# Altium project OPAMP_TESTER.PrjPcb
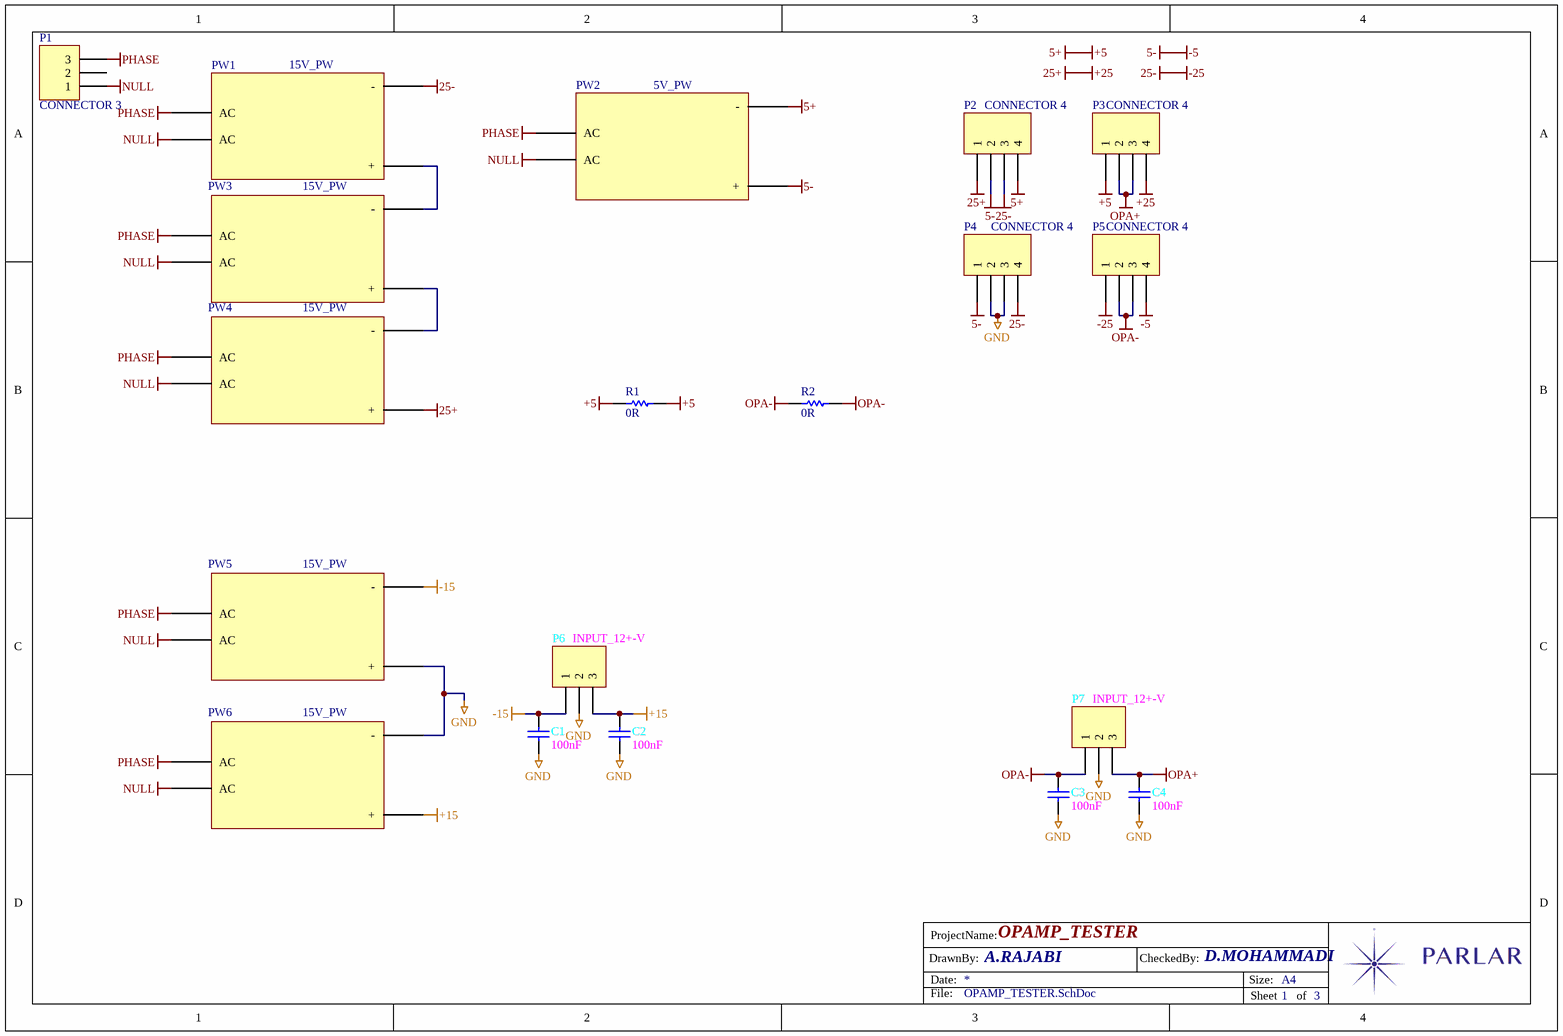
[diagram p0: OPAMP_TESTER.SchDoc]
3 sheets, 148 parts. Net scope: global (net labels, ports and power ports of the same name join across sheets).
Board files: OPAMP_TESTER.PcbDoc, OPAMP_TESTERh.PcbDoc
Sheets:
  OPAMP_TESTER.SchDoc
  OPAMP_TESTER_1.SchDoc
  OPAMP_TESTER_2.SchDoc

## Sheet OPAMP_TESTER.SchDoc: OPAMP_TESTER
size A4; CheckedBy: D.MOHAMMADI; DrawnBy: A.RAJABI; SheetNumber: 1; SheetTotal: 3

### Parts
C1  100nF  [SMD 0805]
C2  100nF  [SMD 0805]
C3  100nF  [SMD 0805]
C4  100nF  [SMD 0805]
P1  CONNECTOR 3  [CON VH 3]
P2  CONNECTOR 4  [CON HDR 2.54M 4]
P3  CONNECTOR 4  [CON HDR 2.54M 4]
P4  CONNECTOR 4  [CON HDR 2.54M 4]
P5  CONNECTOR 4  [CON HDR 2.54M 4]
P6  INPUT_12+-V  [CON XH 3]
P7  INPUT_12+-V  [CON XH 3]
PW1  15V_PW  [POW]
PW2  5V_PW  [POW]
PW3  15V_PW  [POW]
PW4  15V_PW  [POW]
PW5  15V_PW  [POW]
PW6  15V_PW  [POW]
R1  0R  [SMD 1206]
R2  0R  [SMD 1206]

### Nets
+5: P2.4 P3.1 PW2.3(-) R1.1 R1.2  [also labelled 5+]
+15: C2.2 P6.3 PW6.4(+)
+25: P2.1 P3.4 PW4.4(+)  [also labelled 25+]
-5: P2.2 P4.1 P5.4 PW2.4(+)  [also labelled 5-]
-15: C1.2 P6.1 PW5.3(-)
-25: P2.3 P4.4 P5.1 PW1.3(-)  [also labelled 25-]
GND: C1.1 C2.1 C3.1 C4.1 P4.2 P4.3 P6.2 P7.2 PW5.4(+) PW6.3(-)
NULL: P1.1 PW1.2(AC) PW2.2(AC) PW3.2(AC) PW4.2(AC) PW5.2(AC) PW6.2(AC)
OPA+: C4.2 P3.2 P3.3 P7.3
OPA-: C3.2 P5.2 P5.3 P7.1 R2.1 R2.2
PHASE: P1.3 PW1.1(AC) PW2.1(AC) PW3.1(AC) PW4.1(AC) PW5.1(AC) PW6.1(AC)
NetPW1_4: PW1.4(+) PW3.3(-)
NetPW3_4: PW3.4(+) PW4.3(-)

Not connected (* = marked no-connect by the designer): P1 2

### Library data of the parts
C1-C4 = CAP: Capacitor
P1 P6 P7 = CONNECTOR 3: Header, 3-Pin
P2-P5 = CONNECTOR 4: Header, 4-Pin
PW1-PW6 = POWER
R1 R2 = RES: Resistor

## Sheet OPAMP_TESTER_1.SchDoc: OPAMP_TESTER
size A4; CheckedBy: D.MOHAMMADI; DrawnBy: A.RAJABI; SheetNumber: 2; SheetTotal: 3
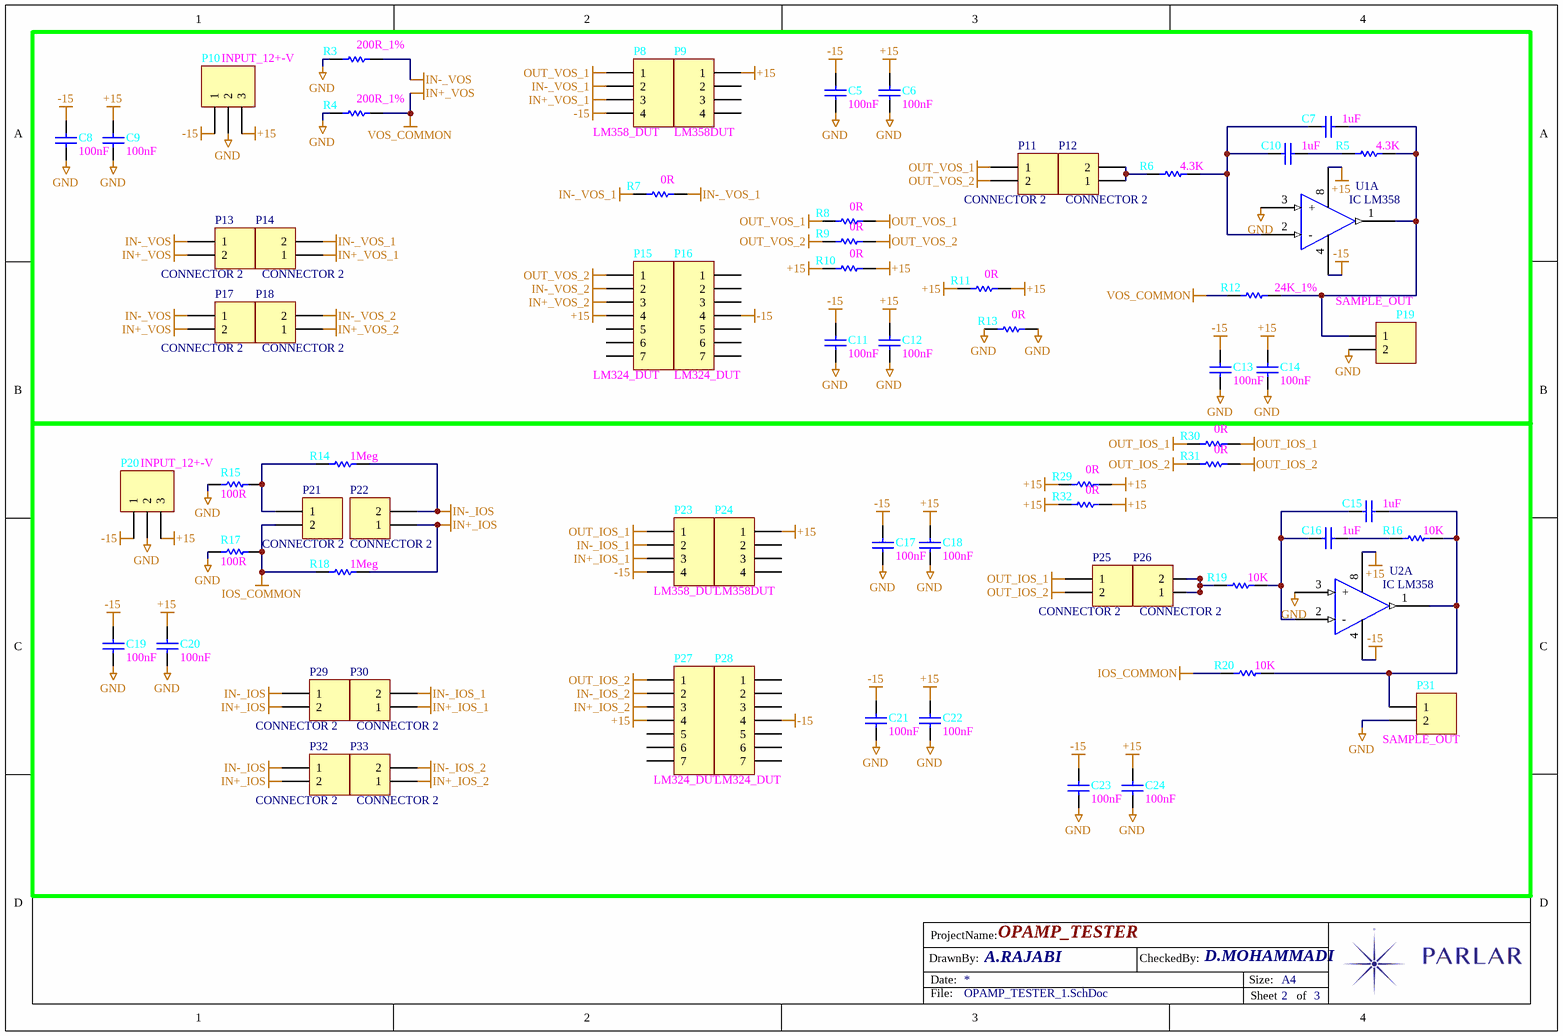
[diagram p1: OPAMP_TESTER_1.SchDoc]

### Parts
C5  100nF  [SMD 0805]
C6  100nF  [SMD 1206]
C7  1uF  [SMD 0805]
C8  100nF  [SMD 0805]
C9  100nF  [SMD 0805]
C10  1uF  [SMD 0805]
C11  100nF  [SMD 0805]
C12  100nF  [SMD 1206]
C13  100nF  [SMD 0805]
C14  100nF  [SMD 0805]
C15  1uF  [SMD 1206]
C16  1uF  [SMD 1206]
C17  100nF  [SMD 0805]
C18  100nF  [SMD 1206]
C19  100nF  [SMD 0805]
C20  100nF  [SMD 0805]
C21  100nF  [SMD 1206]
C22  100nF  [SMD 0805]
C23  100nF  [SMD 0805]
C24  100nF  [SMD 0805]
P8  LM358_DUT  [CON HDR 2.54FM 4]
P9  LM358DUT  [CON HDR 2.54FM 4]
P10  INPUT_12+-V  [CON XH 3]
P11  CONNECTOR 2  [CON HDR 2.54M 2]
P12  CONNECTOR 2  [CON HDR 2.54M 2]
P13  CONNECTOR 2  [CON HDR 2.54M 2]
P14  CONNECTOR 2  [CON HDR 2.54M 2]
P15  LM324_DUT  [CON HDR 2.54FM 7]
P16  LM324_DUT  [CON HDR 2.54FM 7]
P17  CONNECTOR 2  [CON HDR 2.54M 2]
P18  CONNECTOR 2  [CON HDR 2.54M 2]
P19  SAMPLE_OUT  [CON XH 2]
P20  INPUT_12+-V  [CON XH 3]
P21  CONNECTOR 2  [CON HDR 2.54M 2]
P22  CONNECTOR 2  [CON HDR 2.54M 2]
P23  LM358_DUT  [CON HDR 2.54FM 4]
P24  LM358DUT  [CON HDR 2.54FM 4]
P25  CONNECTOR 2  [CON HDR 2.54M 2]
P26  CONNECTOR 2  [CON HDR 2.54M 2]
P27  LM324_DUT  [CON HDR 2.54FM 7]
P28  LM324_DUT  [CON HDR 2.54FM 7]
P29  CONNECTOR 2  [CON HDR 2.54M 2]
P30  CONNECTOR 2  [CON HDR 2.54M 2]
P31  SAMPLE_OUT  [CON XH 2]
P32  CONNECTOR 2  [CON HDR 2.54M 2]
P33  CONNECTOR 2  [CON HDR 2.54M 2]
R3  200R_1%  [SMD 1206]
R4  200R_1%  [SMD 0805]
R5  4.3K  [SMD 0805]
R6  4.3K  [SMD 1206]
R7  0R  [SMD 1206]
R8  0R  [SMD 1206]
R9  0R  [SMD 1206]
R10  0R  [SMD 1206]
R11  0R  [SMD 1206]
R12  24K_1%  [SMD 1206]
R13  0R  [SMD 1206]
R14  1Meg  [SMD 0805]
R15  100R  [SMD 0805]
R16  10K  [SMD 0805]
R17  100R  [SMD 0805]
R18  1Meg  [SMD 0805]
R19  10K  [SMD 1206]
R20  10K  [SMD 0805]
R29  0R  [SMD 1206]
R30  0R  [SMD 1206]
R31  0R  [SMD 1206]
R32  0R  [SMD 1206]
U1  IC LM358  [SMD IC SOP8]  (part A of 2)
U2  IC LM358  [SMD IC SOP8]  (part A of 2)

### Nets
+15: C6.2 C9.2 C12.2 C14.2 C18.2 C20.2 C22.2 C24.2 P9.1 P10.3 P15.4 P20.3 P24.1 P27.4 R10.1 R10.2 R11.1 R11.2 R29.1 R29.2 R32.1 R32.2 U1.8(VCC) U2.8(VCC)
-15: C5.2 C8.2 C11.2 C13.2 C17.2 C19.2 C21.2 C23.2 P8.4 P10.1 P16.4 P20.1 P23.4 P28.4 U1.4(GND) U2.4(GND)
GND: C5.1 C6.1 C8.1 C9.1 C11.1 C12.1 C13.1 C14.1 C17.1 C18.1 C19.1 C20.1 C21.1 C22.1 C23.1 C24.1 P10.2 P19.2 P20.2 P31.2 R3.1 R4.1 R13.1 R13.2 R15.1 R17.1 U1.3(+) U2.3(+)
IN+_IOS: P22.1 P29.2 P32.2 R18.2
IN+_IOS_1: P23.3 P30.1
IN+_IOS_2: P27.3 P33.1
IN+_VOS: P13.2 P17.2 R4.2 R12.1  [also labelled VOS_COMMON]
IN+_VOS_1: P8.3 P14.1
IN+_VOS_2: P15.3 P18.1
IN-_IOS: P22.2 P29.1 P32.1 R14.2
IN-_IOS_1: P23.2 P30.2
IN-_IOS_2: P27.2 P33.2
IN-_VOS: P13.1 P17.1 R3.2
IN-_VOS_1: P8.2 P14.2 R7.1 R7.2
IN-_VOS_2: P15.2 P18.2
IOS_COMMON: P21.2 R17.2 R18.1 R20.1
OUT_IOS_1: P23.1 P25.1 R30.1 R30.2
OUT_IOS_2: P25.2 P27.1 R31.1 R31.2
OUT_VOS_1: P8.1 P11.1 R8.1 R8.2
OUT_VOS_2: P11.2 P15.1 R9.1 R9.2
NetC7_1: C7.1 P19.1 R5.2 R12.2 U1.1(OUT1)
NetC7_2: C7.2 C10.2 R6.2 U1.2(-)
NetC10_1: C10.1 R5.1
NetC15_1: C15.1 P31.1 R16.2 R20.2 U2.1(OUT1)
NetC15_2: C15.2 C16.2 R19.2 U2.2(-)
NetC16_1: C16.1 R16.1
NetP12_1: P12.1 P12.2 R6.1
NetP21_1: P21.1 R14.1 R15.2
NetP26_1: P26.1 P26.2 R19.1

Not connected (* = marked no-connect by the designer): P9 2 3 4; P15 5 6 7; P16 1 2 3 5 6 7; P24 2 3 4; P27 5 6 7; P28 1 2 3 5 6 7

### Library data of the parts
C5-C24 = CAP: Capacitor
P8 P9 P23 P24 = CONNECTOR 4: Header, 4-Pin
P10 P20 = CONNECTOR 3: Header, 3-Pin
P11-P14 P17-P19 P21 P22 P25 P26 P29-P33 = CONNECTOR 2: Header, 2-Pin
P15 P16 P27 P28 = CONNECTOR 7: Header, 7-Pin
R3-R20 R29-R32 = RES: Resistor

## Sheet OPAMP_TESTER_2.SchDoc: OPAMP_TESTER
size A4; CheckedBy: D.MOHAMMADI; DrawnBy: A.RAJABI; SheetNumber: 3; SheetTotal: 3
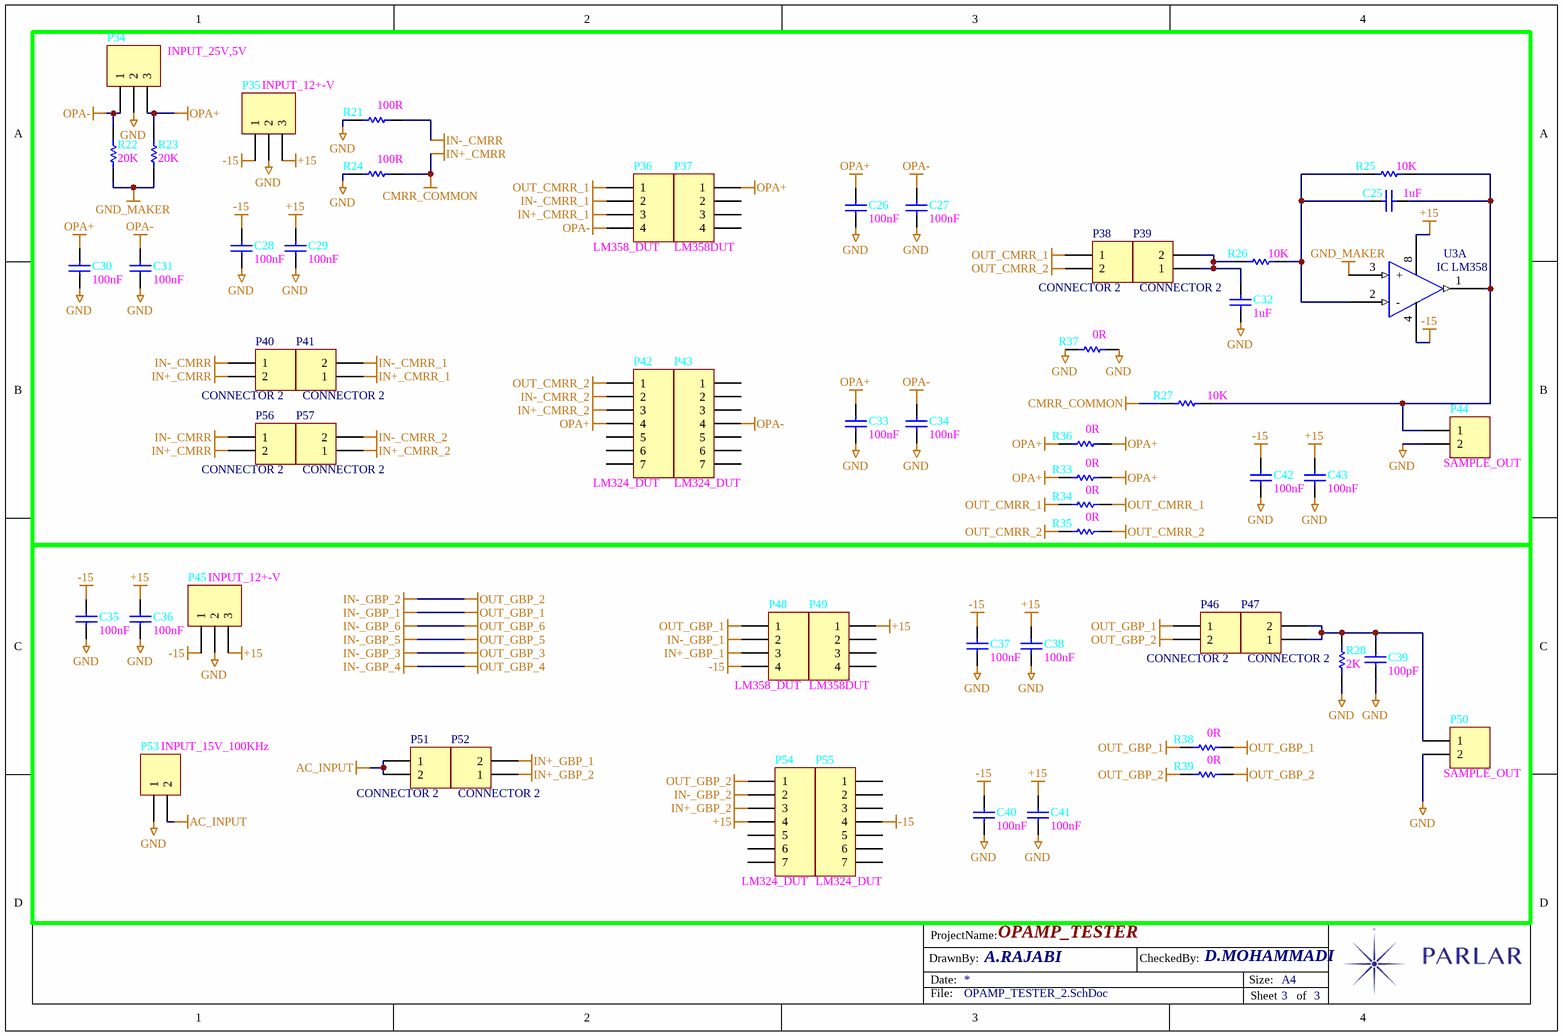
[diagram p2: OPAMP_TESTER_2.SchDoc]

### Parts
C25  1uF  [SMD 1206]
C26  100nF  [SMD 1206]
C27  100nF  [SMD 0805]
C28  100nF  [SMD 0805]
C29  100nF  [SMD 0805]
C30  100nF  [SMD 0805]
C31  100nF  [SMD 0805]
C32  1uF  [SMD 0805]
C33  100nF  [SMD 1206]
C34  100nF  [SMD 0805]
C35  100nF  [SMD 0805]
C36  100nF  [SMD 0805]
C37  100nF  [SMD 0805]
C38  100nF  [SMD 0805]
C39  100pF  [SMD 0805]
C40  100nF  [SMD 0805]
C41  100nF  [SMD 1206]
C42  100nF  [SMD 0805]
C43  100nF  [SMD 0805]
P34  INPUT_25V,5V  [CON XH 3]
P35  INPUT_12+-V  [CON XH 3]
P36  LM358_DUT  [CON HDR 2.54FM 4]
P37  LM358DUT  [CON HDR 2.54FM 4]
P38  CONNECTOR 2  [CON HDR 2.54M 2]
P39  CONNECTOR 2  [CON HDR 2.54M 2]
P40  CONNECTOR 2  [CON HDR 2.54M 2]
P41  CONNECTOR 2  [CON HDR 2.54M 2]
P42  LM324_DUT  [CON HDR 2.54FM 7]
P43  LM324_DUT  [CON HDR 2.54FM 7]
P44  SAMPLE_OUT  [CON XH 2]
P45  INPUT_12+-V  [CON XH 3]
P46  CONNECTOR 2  [CON HDR 2.54M 2]
P47  CONNECTOR 2  [CON HDR 2.54M 2]
P48  LM358_DUT  [CON HDR 2.54FM 4]
P49  LM358DUT  [CON HDR 2.54FM 4]
P50  SAMPLE_OUT  [CON XH 2]
P51  CONNECTOR 2  [CON HDR 2.54M 2]
P52  CONNECTOR 2  [CON HDR 2.54M 2]
P53  INPUT_15V_100KHz  [CON XH 2]
P54  LM324_DUT  [CON HDR 2.54FM 7]
P55  LM324_DUT  [CON HDR 2.54FM 7]
P56  CONNECTOR 2  [CON HDR 2.54M 2]
P57  CONNECTOR 2  [CON HDR 2.54M 2]
R21  100R  [SMD 0805]
R22  20K  [SMD 1206]
R23  20K  [SMD 0805]
R24  100R  [SMD 1206]
R25  10K  [SMD 0805]
R26  10K  [SMD 1206]
R27  10K  [SMD 1206]
R28  2K  [SMD 0805]
R33  0R  [SMD 1206]
R34  0R  [SMD 1206]
R35  0R  [SMD 1206]
R36  0R  [SMD 1206]
R37  0R  [SMD 1206]
R38  0R  [SMD 1206]
R39  0R  [SMD 1206]
U3  IC LM358  [SMD IC SOP8]  (part A of 2)

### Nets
+15: C29.2 C36.2 C38.2 C41.2 C43.2 P35.3 P45.3 P49.1 P54.4 U3.8(VCC)
-15: C28.2 C35.2 C37.2 C40.2 C42.2 P35.1 P45.1 P48.4 P55.4 U3.4(GND)
AC_INPUT: P51.1 P51.2 P53.2
CMRR_COMMON: P40.2 P56.2 R24.2 R27.1  [also labelled IN+_CMRR]
GND: C26.1 C27.1 C28.1 C29.1 C30.1 C31.1 C32.1 C33.1 C34.1 C35.1 C36.1 C37.1 C38.1 C39.1 C40.1 C41.1 C42.1 C43.1 P34.2 P35.2 P44.2 P45.2 P50.2 P53.1 R21.1 R24.1 R28.2 R37.1 R37.2
GND_MAKER: R22.1 R23.1 U3.3(+)
IN+_CMRR_1: P36.3 P41.1
IN+_CMRR_2: P42.3 P57.1
IN+_GBP_1: P48.3 P52.2
IN+_GBP_2: P52.1 P54.3
IN-_CMRR: P40.1 P56.1 R21.2
IN-_CMRR_1: P36.2 P41.2
IN-_CMRR_2: P42.2 P57.2
IN-_GBP_1: P46.1 P48.1 P48.2 R38.1 R38.2  [also labelled OUT_GBP_1]
IN-_GBP_2: P46.2 P54.1 P54.2 R39.1 R39.2  [also labelled OUT_GBP_2]
OPA+: C26.2 C30.2 C33.2 P34.3 P37.1 P42.4 R23.2 R33.1 R33.2 R36.1 R36.2
OPA-: C27.2 C31.2 C34.2 P34.1 P36.4 P43.4 R22.2
OUT_CMRR_1: P36.1 P38.1 R34.1 R34.2
OUT_CMRR_2: P38.2 P42.1 R35.1 R35.2
NetC25_1: C25.1 P44.1 R25.2 R27.2 U3.1(OUT1)
NetC25_2: C25.2 R25.1 R26.2 U3.2(-)
NetC32_2: C32.2 P39.1 P39.2 R26.1
NetC39_2: C39.2 P47.1 P47.2 P50.1 R28.1

Not connected (* = marked no-connect by the designer): P37 2 3 4; P42 5 6 7; P43 1 2 3 5 6 7; P49 2 3 4; P54 5 6 7; P55 1 2 3 5 6 7

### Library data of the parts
C25-C43 = CAP: Capacitor
P34 P35 P45 = CONNECTOR 3: Header, 3-Pin
P36 P37 P48 P49 = CONNECTOR 4: Header, 4-Pin
P38-P41 P44 P46 P47 P50-P53 P56 P57 = CONNECTOR 2: Header, 2-Pin
P42 P43 P54 P55 = CONNECTOR 7: Header, 7-Pin
R21-R28 R33-R39 = RES: Resistor

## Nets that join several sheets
+15: OPAMP_TESTER (C2.2 P6.3 PW6.4), OPAMP_TESTER_1 (24 pins), OPAMP_TESTER_2 (10 pins)
-15: OPAMP_TESTER (C1.2 P6.1 PW5.3), OPAMP_TESTER_1 (16 pins), OPAMP_TESTER_2 (10 pins)
GND: OPAMP_TESTER (10 pins), OPAMP_TESTER_1 (28 pins), OPAMP_TESTER_2 (29 pins)
OPA+: OPAMP_TESTER (C4.2 P3.2 P3.3 P7.3), OPAMP_TESTER_2 (11 pins)
OPA-: OPAMP_TESTER (6 pins), OPAMP_TESTER_2 (7 pins)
